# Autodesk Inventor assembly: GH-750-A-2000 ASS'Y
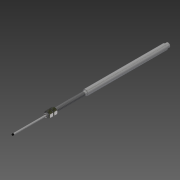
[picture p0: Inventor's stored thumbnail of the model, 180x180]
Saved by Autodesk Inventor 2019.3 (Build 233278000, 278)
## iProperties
Created: 2018-10
Part Number: GH-750-A-2000 ASS'Y
Document SubType Name: Weldment
Designer: Justin
Weld Material: Stainless Steel
Author: Justin
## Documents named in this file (4)
- C:\Users\Justin\Documents\CAD Drawings\The Sensor Connection\3D\LVDT\GH SERIES\GH-750-A-XXXX\GH-750-A-2000\GH-750-A-2000 ASS'Y.iam
- C:\Users\Justin\Documents\CAD Drawings\The Sensor Connection\3D\LVDT\GH SERIES\GH-750-A-XXXX\GH-750-A-2000\GH-750-A-2000 HOUSING_SW.ipt
- C:\Users\Justin\Documents\CAD Drawings\The Sensor Connection\3D\LVDT\GH SERIES\GH-750-A-XXXX\GH-750-A-2000\GH-750-A-2000 SHAFT_SW.ipt
- C:\Users\Justin\Documents\CAD Drawings\The Sensor Connection\3D\LVDT\GH SERIES\GH-750-A-XXXX\GH-750-A-2000\AS 2465 - 1_2  UNF(1).ipt
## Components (4 placed, 3 different names)
1. GH-750-A-2000 HOUSING_SW:1 — Mate:1, Cylindrical:1, Mate:3, Flush:1
2. GH-750-A-2000 SHAFT_SW:1 — Mate:1, Cylindrical:1
3. AS 2465 - Inch 1/2  UNF:1 — Mate:2, Angle:1, Mate:3, Mate:4, Flush:1
4. AS 2465 - Inch 1/2  UNF:2 — Mate:2, Angle:1, Mate:4
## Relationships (7: Mate 4, CylindricalJoint 1, Angle 1, Flush 1)
- Mate:1: GH-750-A-2000 HOUSING_SW:1 ↔ GH-750-A-2000 SHAFT_SW:1
- Cylindrical:1: GH-750-A-2000 HOUSING_SW:1 ↔ GH-750-A-2000 SHAFT_SW:1
- Mate:2: AS 2465 - Inch 1/2  UNF:1 ↔ AS 2465 - Inch 1/2  UNF:2
- Angle:1: AS 2465 - Inch 1/2  UNF:1 ↔ AS 2465 - Inch 1/2  UNF:2
- Mate:3: GH-750-A-2000 HOUSING_SW:1 ↔ AS 2465 - Inch 1/2  UNF:1
- Mate:4: AS 2465 - Inch 1/2  UNF:1 ↔ AS 2465 - Inch 1/2  UNF:2
- Flush:1: GH-750-A-2000 HOUSING_SW:1 ↔ AS 2465 - Inch 1/2  UNF:1
